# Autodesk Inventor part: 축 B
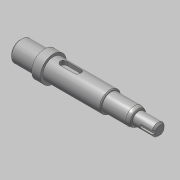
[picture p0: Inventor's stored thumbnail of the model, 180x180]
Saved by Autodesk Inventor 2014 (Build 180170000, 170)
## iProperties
Created: 2020-04
Part Number: 축 B
Material: 강철, 연강
Document SubType Name: Modeling
Designer: mduedu
Density: 7.86 g/cm^3
Appearance: 강철
Mass: 60.8547 g
Surface Area: 31.2855 cm^2
Volume: 7.74232 cm^3
Author: mduedu
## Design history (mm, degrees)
sketch "스케치1"
  geometry: L1 (0, 0)-(14, 0); L2 (14, 0)-(14, 6); L3 (14, 6)-(0, 6); L4 (0, 6)-(0, 0); L5 (14, 0)-(19, 0); L6 (19, 0)-(19, 7.5); L7 (19, 7.5)-(14, 7.5); L8 (14, 7.5)-(14, 0); L9 (19, 0)-(52, 0); L10 (52, 0)-(52, 6); L11 (52, 6)-(19, 6); L12 (19, 6)-(19, 0); L13 (52, 0)-(68, 0); L14 (68, 0)-(68, 5); L15 (68, 5)-(52, 5); L16 (52, 5)-(52, 0); L17 (68, 0)-(80, 0); L18 (80, 0)-(80, 3.5); L19 (80, 3.5)-(68, 3.5); L20 (68, 3.5)-(68, 0)
  constraints: 40 end point, 10 parallel, 5 horizontal, 5 perpendicular
  dimensions: "d0" = 80 distance between parallel lines of L18 L4; "d2" = 14 distance of L2.end L3.end; "d3" = 5 distance of L6.end L7.end; "d5" = 7 diameter of L19 L17; "d6" = 10 diameter of L15 L13; "d7" = 12 diameter of L11 L9; "d8" = 12 diameter of L3 L1; "d9" = 15 diameter of L7 L5; "d35" = 16 distance of L14.end L15.end; "d36" = 52 distance between parallel lines of L10 L4
revolve "회전1" sketch "스케치1" stored, may be unused: angle "d11" = 90 deg
sketch "스케치2"
  geometry: L1 (0, 6)-(0, -6) reference; L2 (0, -6)-(-14, -6) reference; L3 (-14, -6)-(-14, -7.5) reference; L4 (-14, -7.5)-(-19, -7.5) reference; L5 (-19, -7.5)-(-19, -6) reference; L6 (-19, -6)-(-52, -6) reference; L7 (-52, -6)-(-52, -5) reference; L8 (-52, -5)-(-68, -5) reference; L9 (-68, -5)-(-68, -3.5) reference; L10 (-68, -3.5)-(-80, -3.5) reference; L11 (-80, -3.5)-(-80, 3.5) reference; L12 (-80, 3.5)-(-68, 3.5) reference; L13 (-68, 3.5)-(-68, 5) reference; L14 (-68, 5)-(-52, 5) reference; L15 (-52, 5)-(-52, 6) reference; L16 (-52, 6)-(-19, 6) reference; L17 (-19, 6)-(-19, 7.5) reference; L18 (-19, 7.5)-(-14, 7.5) reference; L19 (-14, 7.5)-(-14, 6) reference; L20 (-14, 6)-(0, 6) reference; L21 (-80, 3.5)-(-72, 3.5); L22 (-72, 3.5)-(-72, 2.3); L23 (-72, 2.3)-(-80, 2.3); L24 (-80, 2.3)-(-80, 3.5); 1 further point
  constraints: 8 end point, 2 parallel, 1 horizontal, 1 perpendicular
  dimensions: "d37" = 8 distance of L22.end L23.end; "d38" = 1.2 distance of L21.end L22.end
extrude "돌출1" cut sketch "스케치2" stored distance "d14" = 2; taper "d15" = 0 deg
fillet "모깎기1" dims "d16" = 1
sketch "스케치3"
  geometry: L1 (0, -6)-(0, 6) reference; L2 (0, 6)-(14, 6) reference; L3 (14, 6)-(14, 7.5) reference; L4 (14, 7.5)-(19, 7.5) reference; L5 (19, 7.5)-(19, 6) reference; L6 (19, 6)-(52, 6) reference; L7 (52, 6)-(52, 5) reference; L8 (52, 5)-(68, 5) reference; L9 (68, 5)-(68, 3.5) reference; L10 (68, 3.5)-(80, 3.5) reference; L11 (80, 3.5)-(80, -3.5) reference; L12 (80, -3.5)-(68, -3.5) reference; L13 (68, -3.5)-(68, -5) reference; L14 (68, -5)-(52, -5) reference; L15 (52, -5)-(52, -6) reference; L16 (52, -6)-(19, -6) reference; L17 (19, -6)-(19, -7.5) reference; L18 (19, -7.5)-(14, -7.5) reference; L19 (14, -7.5)-(14, -6) reference; L20 (14, -6)-(0, -6) reference; L21 (23, 6)-(35, 6); L22 (35, 6)-(35, 3.5); L23 (35, 3.5)-(23, 3.5); L24 (23, 3.5)-(23, 6); 1 further point
  constraints: 8 end point, 2 parallel, 1 horizontal, 1 perpendicular, 1 point on line
  dimensions: "d17" = 12 distance of L22.end L23.end; "d18" = 2.5 distance of L21.end L22.end; "d19" = 4 distance from line of L24 L4.end
extrude "돌출2" cut sketch "스케치3" stored distance "d20" = 4; taper "d21" = 0 deg
fillet "모깎기2" dims "d22" = 2
chamfer "모따기1" distance "d23" = 1; stored, may be unused: second distance "d24" = 2, angle "d25" = 45 deg
chamfer "모따기2" distance "d26" = 0.5; stored, may be unused: second distance "d27" = 2, angle "d28" = 45 deg
fillet "모깎기3" dims "d29" = 0.3
chamfer "모따기3" distance "d30" = 1.39; stored, may be unused: second distance "d31" = 2, angle "d32" = 30 deg
fillet "모깎기4" dims "d33" = 4, "d34" = 0.5
node "솔리드1"
node "절단 모서리 투영2"
node "절단 모서리 투영3"
